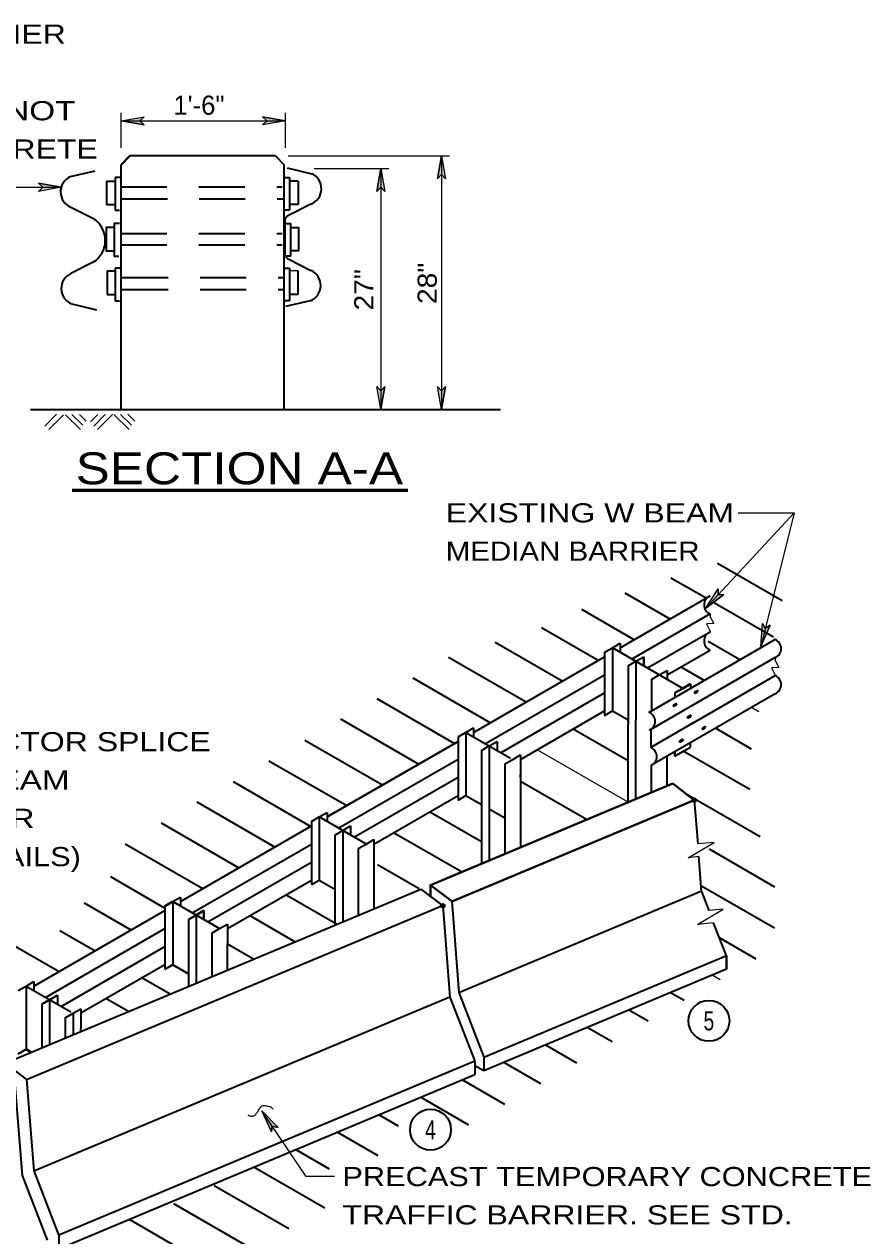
# Model space of a CAD drawing. Extents: x 12.4 to 19.52, y 6.05 to 15.92.
# Drawn here: x 16.636 to 19.286, y 12.12 to 15.915 of the extents above; entities that cross this region are included whole.
import ezdxf
from ezdxf.enums import TextEntityAlignment as Align

# ---------------------------------------------------------------- set-up
doc = ezdxf.new("R2010")
doc.units = 0
doc.header["$LTSCALE"] = 0.024
doc.header["$PDMODE"] = 32
doc.header["$PDSIZE"] = 0.012
doc.linetypes.add('LONG_DASHED', pattern=[7.5, 6, -1.5])
for name, color, linetype, lineweight in [('1', 7, 'Continuous', 35), ('10', 7, 'Continuous', 13), ('12', 7, 'Continuous', 53), ('6', 7, 'Continuous', 13)]:
    doc.layers.add(name, color=color, linetype=linetype, lineweight=lineweight)

msp = doc.modelspace()

# ---------------------------------------------------------------- hatches: boundary and pattern name
at = {"layer": '10'}
for points in [[(17.0105, 15.5999), (16.939, 15.6125), (17.0105, 15.6251), (16.997, 15.6125)], [(17.3817, 15.6251), (17.4532, 15.6125), (17.3817, 15.5999), (17.3952, 15.6125)], [(17.9293, 15.4313), (17.9419, 15.5028), (17.9545, 15.4313), (17.9419, 15.4448)], [(17.7392, 15.3917), (17.7518, 15.4632), (17.7644, 15.3917), (17.7518, 15.4052)], [(16.6798, 15.4172), (16.7513, 15.4046), (16.6798, 15.392), (16.6933, 15.4046)], [(17.7644, 14.7808), (17.7518, 14.7093), (17.7392, 14.7808), (17.7518, 14.7673)], [(17.9545, 14.7807), (17.9419, 14.7092), (17.9293, 14.7807), (17.9419, 14.7672)], [(18.8261, 14.1293), (18.7682, 14.0855), (18.8076, 14.1465), (18.8077, 14.128)], [(18.971, 14.0327), (18.9414, 13.9664), (18.9465, 14.0388), (18.9555, 14.0227)], [(17.4092, 12.4458), (17.3797, 12.5121), (17.4301, 12.4599), (17.4121, 12.464)]]:
    msp.add_hatch(color=256, dxfattribs=at).paths.add_polyline_path(points)

# ---------------------------------------------------------------- linework, layer by layer
at = {"layer": '1', "lineweight": 40}
for p, q in [((16.939, 15.4754), (16.9672, 15.5039)), ((18.5749, 13.934), (18.5749, 13.9067)), ((18.6727, 13.8209), (18.6972, 13.835)), ((18.6972, 13.835), (18.7217, 13.8492)), ((18.721, 13.7504), (18.7126, 13.7456)), ((18.7141, 13.7432), (18.7224, 13.748)), ((18.526, 13.7361), (18.526, 13.7297)), ((17.5836, 13.4324), (17.9936, 13.6691)), ((17.9936, 13.6832), (18.0181, 13.6973)), ((18.6961, 13.6751), (18.6877, 13.6703)), ((18.6892, 13.6678), (18.6976, 13.6726)), ((18.6727, 13.6231), (18.6727, 13.6372)), ((18.1894, 13.5557), (18.1894, 13.5648)), ((18.7333, 13.4851), (18.6661, 13.5369)), ((18.7333, 13.4851), (17.9742, 13.1672)), ((17.9074, 13.2192), (17.9074, 13.181)), ((17.0758, 13.1532), (17.1003, 13.1675)), ((17.1737, 13.125), (17.1982, 13.1391)), ((17.1982, 13.1391), (17.1982, 13.1119)), ((17.1493, 13.1109), (17.1737, 13.125)), ((18.8338, 12.9551), (18.8338, 12.9974)), ((17.0758, 12.9554), (17.1003, 12.9695)), ((17.1003, 12.9695), (17.1493, 12.9413)), ((17.2471, 12.9413), (17.2471, 12.9425)), ((16.6903, 12.8459), (16.7148, 12.86)), ((16.6414, 12.7046), (16.658, 12.695))]:
    msp.add_line(p, q, dxfattribs=at)
at = {"layer": '1'}
for p, q in [((16.9672, 15.5039), (17.4214, 15.5039)), ((17.4214, 15.5039), (17.4497, 15.4754)), ((16.8569, 15.4556), (16.7795, 15.4377)), ((16.939, 14.7092), (16.939, 15.4754)), ((17.4497, 14.7092), (17.4497, 15.4754)), ((17.4583, 15.4653), (17.5357, 15.4474)), ((16.7818, 15.3425), (16.8527, 15.3066)), ((17.5333, 15.3521), (17.4625, 15.3163)), ((17.4511, 15.3035), (17.4511, 15.1913)), ((16.8516, 15.1698), (16.7818, 15.1346)), ((17.4636, 15.1795), (17.5333, 15.1442)), ((16.7841, 15.0392), (16.8614, 15.0213)), ((17.5311, 15.0489), (17.4538, 15.031)), ((16.655, 14.7092), (18.127, 14.7092)), ((19.0081, 14.1095), (18.8061, 14.2261)), ((18.77, 14.1173), (18.6601, 14.1808)), ((18.5014, 13.9622), (18.7827, 14.1246)), ((18.6575, 14.0523), (18.5166, 14.1337)), ((18.545, 13.9874), (18.3811, 14.082)), ((18.9813, 13.9951), (18.7961, 14.102)), ((18.7827, 14.0682), (18.538, 13.9269)), ((18.4325, 13.9224), (18.2554, 14.0246)), ((18.7827, 14.0117), (18.587, 13.8987)), ((18.32, 13.8575), (18.1101, 13.9787)), ((18.477, 13.9622), (18.5014, 13.9764)), ((18.5014, 13.9764), (18.5014, 13.9472)), ((18.9866, 13.988), (18.5896, 13.7588)), ((18.777, 13.9832), (18.8776, 13.925)), ((17.9642, 13.9331), (18.2074, 13.7925)), ((18.0425, 13.6973), (18.4525, 13.934)), ((18.4525, 13.9481), (18.477, 13.9622)), ((18.4525, 13.9481), (18.4525, 13.7503)), ((18.6972, 13.835), (18.477, 13.9622)), ((18.477, 13.9622), (18.477, 13.7644)), ((18.5504, 13.9199), (18.5749, 13.934)), ((18.9866, 13.9315), (18.5968, 13.7064)), ((18.6483, 13.8776), (18.7827, 13.9553)), ((18.526, 13.9058), (18.5504, 13.9199)), ((18.526, 13.9058), (18.526, 13.722)), ((18.5504, 13.9199), (18.5504, 13.7362)), ((18.6238, 13.8775), (18.6483, 13.8916)), ((18.6483, 13.8916), (18.6483, 13.8647)), ((18.6916, 13.9025), (18.765, 13.8601)), ((17.8517, 13.8681), (18.095, 13.7276)), ((18.0792, 13.662), (18.4525, 13.8776)), ((18.5994, 13.8633), (18.6238, 13.8775)), ((18.5994, 13.8633), (18.5994, 13.7644)), ((18.734, 13.7291), (18.9866, 13.875)), ((18.9866, 13.8776), (18.9866, 13.8749)), ((18.1282, 13.6338), (18.4525, 13.8211)), ((18.9866, 13.8184), (18.6013, 13.5959)), ((18.6727, 13.8209), (18.6727, 13.8068)), ((18.7217, 13.8492), (18.7217, 13.835)), ((18.7429, 13.8278), (18.7345, 13.823)), ((18.736, 13.8205), (18.7443, 13.8253)), ((17.7392, 13.8032), (17.9825, 13.6627)), ((18.6762, 13.7871), (18.6679, 13.7823)), ((18.6693, 13.7798), (18.6776, 13.7846)), ((17.87, 13.5977), (17.6267, 13.7382)), ((18.1894, 13.6127), (18.4525, 13.7645)), ((18.4525, 13.7503), (18.477, 13.7644)), ((18.477, 13.7644), (18.526, 13.7361)), ((18.0181, 13.6973), (18.0425, 13.7114)), ((18.0425, 13.7114), (18.0425, 13.6823)), ((18.526, 13.6085), (18.3542, 13.7078)), ((18.526, 13.4783), (18.526, 13.722)), ((18.5504, 13.4885), (18.5504, 13.7362)), ((18.5968, 13.7064), (18.5968, 13.6502)), ((18.734, 13.7291), (18.597, 13.6499)), ((18.7668, 13.7147), (18.7584, 13.7099)), ((18.7598, 13.7075), (18.7682, 13.7123)), ((18.9126, 13.645), (18.7994, 13.7103)), ((17.5142, 13.6733), (17.7575, 13.5328)), ((17.9936, 13.6832), (17.9936, 13.4853)), ((18.0181, 13.6973), (18.1584, 13.6163)), ((18.0181, 13.6973), (18.0181, 13.4995)), ((18.0915, 13.6549), (18.116, 13.6691)), ((18.116, 13.6691), (18.116, 13.6418)), ((18.7217, 13.6514), (18.7217, 13.6655)), ((18.067, 13.6408), (18.0915, 13.6549)), ((18.067, 13.6408), (18.067, 13.286)), ((18.0915, 13.6549), (18.0915, 13.2963)), ((18.165, 13.6125), (18.1894, 13.6266)), ((18.1894, 13.6266), (18.1894, 13.3373)), ((18.907, 13.5184), (18.6986, 13.6387)), ((17.4017, 13.6083), (17.645, 13.4678)), ((17.9936, 13.6127), (17.6203, 13.397)), ((18.1405, 13.5984), (18.165, 13.6125)), ((18.1405, 13.5984), (18.1405, 13.3168)), ((18.5994, 13.5089), (18.5994, 13.5948)), ((18.6483, 13.5295), (18.6483, 13.6231)), ((17.9936, 13.5561), (17.6692, 13.3688)), ((17.2892, 13.5433), (17.5325, 13.4028)), ((18.3961, 13.4239), (18.1894, 13.5432)), ((17.42, 13.3379), (17.1767, 13.4783)), ((17.7305, 13.3476), (17.9936, 13.4996)), ((17.9936, 13.4853), (18.0181, 13.4995)), ((18.0181, 13.4995), (18.067, 13.4712)), ((18.9394, 13.3697), (18.7148, 13.4993)), ((18.7333, 13.4851), (18.744, 13.348)), ((17.5591, 13.4324), (17.5836, 13.4465)), ((17.5836, 13.4465), (17.5836, 13.4174)), ((18.067, 13.354), (17.9072, 13.4463)), ((18.1405, 13.4288), (18.0915, 13.4571)), ((17.0642, 13.4135), (17.3075, 13.2729)), ((17.1248, 13.1675), (17.5347, 13.4041)), ((17.5347, 13.4182), (17.5591, 13.4324)), ((17.5347, 13.4182), (17.5347, 13.2204)), ((17.5591, 13.4324), (17.5591, 13.2346)), ((17.7103, 13.3451), (17.5591, 13.4324)), ((17.6326, 13.39), (17.6571, 13.4041)), ((17.6571, 13.4041), (17.6571, 13.3768)), ((17.6081, 13.3758), (17.6326, 13.39)), ((17.6081, 13.3758), (17.6081, 13.1897)), ((17.6326, 13.39), (17.6326, 13.2039)), ((17.7061, 13.3476), (17.7305, 13.3617)), ((17.7305, 13.3617), (17.7305, 13.3348)), ((18.0049, 13.26), (17.7918, 13.383)), ((16.9517, 13.3484), (17.195, 13.208)), ((17.1614, 13.1321), (17.5347, 13.3476)), ((17.6815, 13.3334), (17.7061, 13.3476)), ((17.6815, 13.3334), (17.6815, 13.2322)), ((17.7305, 13.3348), (17.7305, 13.1451)), ((18.986, 13.2128), (18.7814, 13.331)), ((17.2104, 13.1039), (17.5347, 13.2911)), ((18.7556, 13.1993), (18.7471, 13.308)), ((16.9051, 13.2455), (17.0758, 13.1469)), ((17.8717, 13.207), (17.7416, 13.2821)), ((16.5757, 12.6615), (17.8774, 13.2067)), ((17.2716, 13.0827), (17.5347, 13.2346)), ((17.5347, 13.2204), (17.5591, 13.2346)), ((17.5591, 13.2346), (17.6081, 13.2063)), ((17.6815, 13.2322), (17.6815, 13.1246)), ((18.9842, 13.084), (18.7543, 13.2168)), ((17.1003, 13.1675), (17.1248, 13.1816)), ((17.1248, 13.1816), (17.1248, 13.1524)), ((17.6136, 13.0961), (17.4577, 13.1862)), ((17.6081, 13.2063), (17.6081, 13.0939)), ((17.6326, 13.2039), (17.6326, 13.1042)), ((18.7537, 13.1984), (17.9965, 12.8813)), ((18.7556, 13.1993), (18.7787, 13.1397)), ((16.6431, 12.6098), (17.9454, 13.1552)), ((16.6659, 12.9024), (17.0758, 13.1391)), ((16.9701, 13.0781), (16.8244, 13.1622)), ((17.0758, 13.1532), (17.0758, 12.9554)), ((17.1003, 13.1675), (17.2471, 13.0826)), ((17.1003, 13.1675), (17.1003, 12.9695)), ((17.1493, 13.1109), (17.1493, 12.9017)), ((17.1737, 13.125), (17.1737, 12.912)), ((17.2471, 13.0826), (17.2716, 13.0967)), ((17.2716, 13.0967), (17.2716, 13.0349)), ((17.4832, 13.0416), (17.3424, 13.1229)), ((18.8338, 12.9974), (18.7936, 13.1012)), ((16.7026, 12.8671), (17.0758, 13.0827)), ((16.747, 13.077), (16.8576, 13.0131)), ((17.2227, 13.0685), (17.2471, 13.0826)), ((17.2227, 13.0685), (17.2227, 12.9325)), ((16.6075, 13.0276), (16.7451, 12.9482)), ((16.7515, 12.8389), (17.0758, 13.0262)), ((17.2716, 12.953), (17.2716, 13.0349)), ((17.3528, 12.9869), (17.2716, 13.0338)), ((18.9266, 12.9873), (18.8121, 13.0534)), ((17.0758, 12.9696), (16.8127, 12.8177)), ((18.8338, 12.9551), (18.0744, 12.637)), ((16.6414, 12.9024), (16.6659, 12.9166)), ((16.6659, 12.9166), (16.6659, 12.8874)), ((17.092, 12.8777), (17.002, 12.9298)), ((16.6169, 12.8883), (16.6414, 12.9024)), ((16.6414, 12.9024), (16.7816, 12.8215)), ((16.6414, 12.9024), (16.6414, 12.7046)), ((16.6651, 12.3239), (17.9676, 12.8693)), ((16.7148, 12.86), (16.7393, 12.8741)), ((16.7393, 12.8741), (16.7393, 12.847)), ((18.7016, 12.8574), (18.6592, 12.8819)), ((16.6903, 12.8459), (16.6903, 12.707)), ((16.7148, 12.86), (16.7148, 12.7164)), ((16.7882, 12.8177), (16.8127, 12.8318)), ((16.8127, 12.8318), (16.8127, 12.77)), ((16.9616, 12.8231), (16.8946, 12.8618)), ((18.5891, 12.7925), (18.5288, 12.8273)), ((16.7638, 12.8036), (16.7882, 12.8177)), ((16.7638, 12.8036), (16.7638, 12.7403)), ((16.7882, 12.8177), (16.7882, 12.7505)), ((16.8127, 12.7607), (16.8127, 12.77)), ((18.4767, 12.7275), (18.3984, 12.7727)), ((18.268, 12.7181), (18.3642, 12.6626)), ((16.6169, 12.6905), (16.6414, 12.7046)), ((16.5757, 12.6615), (16.6431, 12.6098)), ((18.0459, 12.6674), (16.7435, 12.122)), ((18.0463, 12.6663), (18.0463, 12.6252)), ((18.0744, 12.637), (18.0463, 12.6532)), ((18.1376, 12.6635), (18.2517, 12.5976)), ((16.6429, 12.6099), (16.6651, 12.3239)), ((16.7434, 12.0796), (18.0463, 12.6252)), ((18.0073, 12.6089), (18.1392, 12.5327)), ((17.8768, 12.5543), (18.0267, 12.4677)), ((17.7464, 12.4997), (17.8063, 12.4651)), ((17.616, 12.4451), (17.7424, 12.372)), ((17.4856, 12.3905), (17.5903, 12.33)), ((17.358, 12.3343), (17.5768, 12.208)), ((16.6651, 12.324), (16.743, 12.1232)), ((17.2301, 12.2782), (17.4642, 12.143)), ((17.1033, 12.2216), (17.3518, 12.078)), ((16.9639, 12.172), (17.2392, 12.0131)), ((16.7434, 12.1222), (16.7434, 12.0796))]:
    msp.add_line(p, q, dxfattribs=at)
at = {"layer": '1', "linetype": 'LONG_DASHED'}
for p, q in [((16.8934, 15.4244), (16.9204, 15.4244)), ((16.8934, 15.4244), (16.8934, 15.3504)), ((17.4931, 15.4244), (17.4661, 15.4244)), ((17.4931, 15.4244), (17.4931, 15.3504)), ((16.9382, 15.4062), (17.4434, 15.4062)), ((16.8934, 15.3504), (16.9187, 15.3504)), ((16.9397, 15.3686), (17.4448, 15.3686)), ((17.4931, 15.3504), (17.4679, 15.3504)), ((16.9382, 15.2598), (17.4434, 15.2598)), ((16.9382, 15.2249), (17.4434, 15.2249)), ((16.8949, 15.1427), (16.9204, 15.1427)), ((16.8949, 15.1427), (16.8949, 15.0687)), ((17.4917, 15.1427), (17.4917, 15.0687)), ((16.9424, 15.1217), (17.4476, 15.1217)), ((16.8949, 15.0687), (16.9201, 15.0687)), ((16.9425, 15.0841), (17.4476, 15.0841)), ((17.4917, 15.0687), (17.4664, 15.0687))]:
    msp.add_line(p, q, dxfattribs=at)
at = {"layer": '1', "linetype": 'LONG_DASHED', "lineweight": 25}
msp.add_line((17.4917, 15.1427), (17.4661, 15.1427), dxfattribs=at)
at = {"layer": '1', "lineweight": 25}
for p, q in [((18.7827, 14.0682), (18.7827, 14.0597)), ((18.7827, 14.015), (18.7827, 14.0114)), ((18.9866, 13.9315), (18.9866, 13.9226)), ((18.9352, 13.7618), (18.9121, 13.7752)), ((18.5265, 13.4785), (18.2417, 13.6429)), ((18.8141, 12.9224), (18.7896, 12.9365))]:
    msp.add_line(p, q, dxfattribs=at)
at = {"layer": '1', "linetype": 'LONG_DASHED'}
for points in [[(16.9369, 15.4355), (16.92, 15.4355), (16.92, 15.3333), (16.9341, 15.3333)], [(17.4497, 15.4355), (17.4665, 15.4355), (17.4665, 15.3333), (17.4525, 15.3333)], [(16.9369, 15.151), (16.92, 15.151), (16.92, 15.0488), (16.9341, 15.0488)], [(17.4497, 15.151), (17.4665, 15.151), (17.4665, 15.0488), (17.4525, 15.0488)]]:
    msp.add_lwpolyline(points, dxfattribs=at)
at = {"layer": '1'}
for points in [[(16.9173, 15.2793), (16.8921, 15.2793), (16.8921, 15.2054), (16.9166, 15.2054)], [(16.9341, 15.2912), (16.9172, 15.2912), (16.9172, 15.189), (16.9312, 15.189)], [(17.4525, 15.2912), (17.4694, 15.2912), (17.4694, 15.189), (17.4553, 15.189)], [(17.4693, 15.2793), (17.4945, 15.2793), (17.4945, 15.2054), (17.47, 15.2054)], [(18.6727, 13.6231), (18.6972, 13.6372), (18.7217, 13.6514)], [(17.8774, 13.2067), (17.9458, 13.154), (17.9681, 12.8682), (18.0459, 12.6674)], [(17.9739, 13.1681), (17.9962, 12.8822), (18.0744, 12.6803)], [(18.8321, 12.9967), (18.0744, 12.6794), (18.0744, 12.637)], [(16.7079, 12.1071), (16.6297, 12.309), (16.6073, 12.5948)]]:
    msp.add_lwpolyline(points, dxfattribs=at)
at = {"layer": '1', "lineweight": 40}
msp.add_lwpolyline([(18.6661, 13.537), (17.9074, 13.2192), (17.9739, 13.1681)], dxfattribs=at)
at = {"layer": '1'}
for centre, radius, start, end in [((17.5141, 15.40021), 0.05183, 291.78198, 65.51256), ((16.80099, 15.39054), 0.05183, 114.48744, 248.21802), ((16.80777, 15.2386), 0.08149, 302.4782, 56.5792), ((17.47473, 15.29387), 0.02555, 118.62654, 157.80443), ((17.48012, 15.20976), 0.03445, 212.55091, 241.31028), ((17.51186, 15.09708), 0.05183, 291.78198, 65.51256), ((16.80324, 15.08741), 0.05183, 114.48744, 248.21802), ((18.79444, 14.09637), 0.0306, 112.56091, 247.43909), ((18.79444, 13.98346), 0.0306, 112.56091, 247.43909), ((18.97486, 13.95978), 0.0306, 292.56091, 67.43909), ((18.97486, 13.8467), 0.0306, 292.56091, 67.43909), ((18.73538, 13.82183), 0.00143, 126.00901, 293.99099), ((18.74347, 13.82649), 0.00143, 306.009, 113.99099), ((18.6687, 13.78118), 0.00143, 126.00901, 293.99099), ((18.67679, 13.78584), 0.00143, 306.009, 113.99099), ((18.58014, 13.732), 0.0306, 292.56091, 67.43909), ((18.75927, 13.7088), 0.00143, 126.00901, 293.99099), ((18.76735, 13.71347), 0.00143, 306.009, 113.99099), ((18.58539, 13.62165), 0.0306, 292.56091, 67.43909)]:
    msp.add_arc(centre, radius, start, end, dxfattribs=at)
at = {"layer": '1', "lineweight": 40}
for centre, start, end in [((18.71348, 13.7445), 126.00901, 293.99099), ((18.72157, 13.74917), 306.009, 113.99099), ((18.68862, 13.66913), 126.00901, 293.99099), ((18.6967, 13.67379), 306.009, 113.99099)]:
    msp.add_arc(centre, 0.00143, start, end, dxfattribs=at)
at = {"layer": '1'}
for p in [(18.7333, 13.4851), (17.9458, 13.154)]:
    msp.add_point(p, dxfattribs=at)
at = {"layer": '10'}
for p, q in [((16.939, 15.5284), (16.939, 15.6375)), ((17.4532, 15.5284), (17.4532, 15.6375)), ((16.939, 15.6125), (17.0105, 15.6251)), ((16.939, 15.6125), (17.4532, 15.6125)), ((16.939, 15.6125), (17.0105, 15.5999)), ((17.4532, 15.6125), (17.3817, 15.6251)), ((17.4532, 15.6125), (17.3817, 15.5999)), ((17.4617, 15.5028), (17.9669, 15.5028)), ((17.9419, 15.5028), (17.9293, 15.4313)), ((17.9419, 15.5028), (17.9419, 14.7092)), ((17.9419, 15.5028), (17.9545, 15.4313)), ((17.5435, 15.4632), (17.7768, 15.4632)), ((17.7518, 15.4632), (17.7392, 15.3917)), ((17.7518, 15.4632), (17.7518, 14.7093)), ((17.7518, 15.4632), (17.7644, 15.3917)), ((16.7513, 15.4046), (16.6798, 15.4172)), ((15.9072, 15.4046), (16.7513, 15.4046)), ((16.7513, 15.4046), (16.6798, 15.392)), ((17.7518, 14.7093), (17.7392, 14.7808)), ((17.7518, 14.7093), (17.7644, 14.7808)), ((17.9419, 14.7092), (17.9293, 14.7807)), ((17.9419, 14.7092), (17.9545, 14.7807)), ((19.0462, 14.3849), (18.9414, 13.9664)), ((18.7682, 14.0855), (18.8076, 14.1465)), ((18.7682, 14.0855), (18.8261, 14.1293)), ((18.9414, 13.9664), (18.9465, 14.0388)), ((18.9414, 13.9664), (18.971, 14.0327)), ((18.714, 13.3043), (18.7953, 13.352)), ((18.7953, 13.352), (18.744, 13.348)), ((18.7471, 13.308), (18.714, 13.3043)), ((18.743, 13.0955), (18.8242, 13.1433)), ((18.8242, 13.1433), (18.7787, 13.1397)), ((18.7936, 13.1012), (18.743, 13.0955)), ((17.3797, 12.5121), (17.4092, 12.4458)), ((17.3797, 12.5121), (17.4301, 12.4599))]:
    msp.add_line(p, q, dxfattribs=at)
for points in [[(17.0105, 15.5999), (16.939, 15.6125), (17.0105, 15.6251), (16.997, 15.6125)], [(17.3817, 15.6251), (17.4532, 15.6125), (17.3817, 15.5999), (17.3952, 15.6125)], [(17.9293, 15.4313), (17.9419, 15.5028), (17.9545, 15.4313), (17.9419, 15.4448)], [(17.7392, 15.3917), (17.7518, 15.4632), (17.7644, 15.3917), (17.7518, 15.4052)], [(16.6798, 15.4172), (16.7513, 15.4046), (16.6798, 15.392), (16.6933, 15.4046)], [(17.7644, 14.7808), (17.7518, 14.7093), (17.7392, 14.7808), (17.7518, 14.7673)], [(17.9545, 14.7807), (17.9419, 14.7092), (17.9293, 14.7807), (17.9419, 14.7672)], [(18.8261, 14.1293), (18.7682, 14.0855), (18.8076, 14.1465), (18.8077, 14.128)], [(18.971, 14.0327), (18.9414, 13.9664), (18.9465, 14.0388), (18.9555, 14.0227)], [(17.4092, 12.4458), (17.3797, 12.5121), (17.4301, 12.4599), (17.4121, 12.464)]]:
    msp.add_lwpolyline(points, close=True, dxfattribs=at)
for points in [[(17.0105, 15.5999), (16.997, 15.6125), (17.0105, 15.6251)], [(17.3817, 15.6251), (17.3952, 15.6125), (17.3817, 15.5999)], [(16.6798, 15.4172), (16.6933, 15.4046), (16.6798, 15.392)], [(17.9293, 15.4313), (17.9419, 15.4448), (17.9545, 15.4313)], [(17.7392, 15.3917), (17.7518, 15.4052), (17.7644, 15.3917)], [(17.7644, 14.7808), (17.7518, 14.7673), (17.7392, 14.7808)], [(17.9545, 14.7807), (17.9419, 14.7672), (17.9293, 14.7807)], [(18.8708, 14.3849), (19.0462, 14.3849), (18.7682, 14.0855)], [(18.8261, 14.1293), (18.8077, 14.128), (18.8076, 14.1465)], [(18.7827, 14.0597), (18.7946, 14.0379), (18.7714, 14.0372), (18.7827, 14.0145)], [(18.971, 14.0327), (18.9555, 14.0227), (18.9465, 14.0388)], [(18.9866, 13.9226), (18.9985, 13.9007), (18.9753, 13.8999), (18.9866, 13.8773)], [(17.6066, 12.3059), (17.5187, 12.3059), (17.3797, 12.5121)], [(17.4092, 12.4458), (17.4121, 12.464), (17.4301, 12.4599)]]:
    msp.add_lwpolyline(points, dxfattribs=at)
at = {"layer": '10', "lineweight": 35}
for centre in [(18.77908, 12.79382), (17.90743, 12.45276)]:
    msp.add_circle(centre, 0.06414, dxfattribs=at)
at = {"layer": '10'}
msp.add_spline([(17.3359, 12.4997), (17.3391, 12.4969), (17.3428, 12.4959), (17.3464, 12.4949), (17.3506, 12.4958), (17.3548, 12.4966), (17.3595, 12.4993), (17.3645, 12.5069), (17.3674, 12.5101), (17.3712, 12.517), (17.3785, 12.5259), (17.3832, 12.5286), (17.3881, 12.5283), (17.3947, 12.5275), (17.4022, 12.5255), (17.4077, 12.524), (17.4134, 12.5195), (17.4152, 12.519)], degree=3, dxfattribs=at)
at = {"layer": '12'}
msp.add_line((16.7856, 14.4558), (17.8368, 14.4558), dxfattribs=at)
at = {"layer": '6'}
for p, q in [((16.7369, 14.6936), (16.7005, 14.6565)), ((16.7127, 14.6457), (16.7584, 14.6924)), ((16.7645, 14.6924), (16.8114, 14.6465)), ((16.8191, 14.6591), (16.785, 14.6926)), ((16.8085, 14.6927), (16.8291, 14.6725)), ((16.8426, 14.6696), (16.8655, 14.693)), ((16.8891, 14.6931), (16.8531, 14.6566)), ((16.8652, 14.6457), (16.9119, 14.6933)), ((16.9162, 14.6933), (16.9639, 14.6465)), ((16.9717, 14.6591), (16.9367, 14.6934)), ((16.9602, 14.6936), (16.9816, 14.6725))]:
    msp.add_line(p, q, dxfattribs=at)

# ---------------------------------------------------------------- texts
at = {"layer": '12'}
for s, width, p in [('THE EXISTING TRAFFIC BARRIER', 1.25, (15.1442, 15.8546)), ('TRAFFIC LANE SIDE, SHALL NOT', 1.3, (15.1442, 15.6146)), ('BE ANCHORED TO THE CONCRETE', 1.25, (15.1442, 15.4946)), ('EXISTING W BEAM', 1.25, (17.9552, 14.3549)), ('MEDIAN BARRIER', 1.15, (17.9552, 14.2349)), ('W BEAM TERMINAL CONNECTOR SPLICE', 1.25, (15.2188, 13.6381)), ('BOLTED TO EXISTING W BEAM', 1.3, (15.2188, 13.5181)), ('(SEE STD. MD 104.01-48 FOR', 1.3, (15.2188, 13.3981)), ('TERMINAL CONNECTOR DETAILS)', 1.2, (15.2188, 13.2781)), ('PRECAST TEMPORARY CONCRETE', 1.2, (17.6316, 12.2759)), ('TRAFFIC BARRIER. SEE STD.', 1.25, (17.6316, 12.1559))]:
    msp.add_text(s, height=0.06, dxfattribs=dict(at, width=width)).set_placement(p)
msp.add_text('1\'-6"', height=0.06, dxfattribs=at).set_placement((17.1027, 15.6319))
at = {"layer": '12', "width": 1.1}
for s, p in [('27"', (17.7287, 15.0837)), ('28"', (17.927, 15.1038))]:
    msp.add_text(s, height=0.06, rotation=90, dxfattribs=at).set_placement(p, align=Align.CENTER)
at = {"layer": '12'}
for s, height, width, p in [('SECTION A-A', 0.1, 1.2, (17.3091, 14.4744)), ('5', 0.06, 0.75, (18.779, 12.7638)), ('4', 0.06, 0.75, (17.9074, 12.4226))]:
    msp.add_text(s, height=height, dxfattribs=dict(at, width=width)).set_placement(p, align=Align.CENTER)

doc.saveas('drawing.dxf')
